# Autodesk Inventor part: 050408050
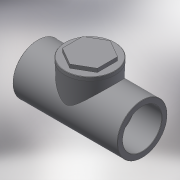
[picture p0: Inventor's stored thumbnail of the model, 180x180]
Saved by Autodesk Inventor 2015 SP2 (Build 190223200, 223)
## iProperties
Created: 2017-10
Part Number: 050408050
Material: Generic
Description: PLASSON CHECK VALVE T-CLAPPERALVE-CEMENT 50
Document SubType Name: Modeling
Designer: KIM
Density: 1 g/cm^3
Appearance: Default
Author: KIM
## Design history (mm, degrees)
derived "050408.ipt"
feature "Solid1::050408.ipt"
feature "Solid2::050408.ipt"
tag "TaggingFeature1"
body "Solid1"
other parameters: "d0" = 123, "d1" = 62, "d2" = 31, "d5" = 40.3605, "d7" = 0.44845, "d8" = 31, "d15" = 0, "d18" = 44.845, "d24" = 0.44845, "d37" = 43.4, "d38" = 5, "d39" = 0, "d41" = 62, "d42" = 5, "d43" = 58.9, "G_" = 44.845, "E_" = 62, "H_" = 123, "lt_" = 13, "l_" = 31
